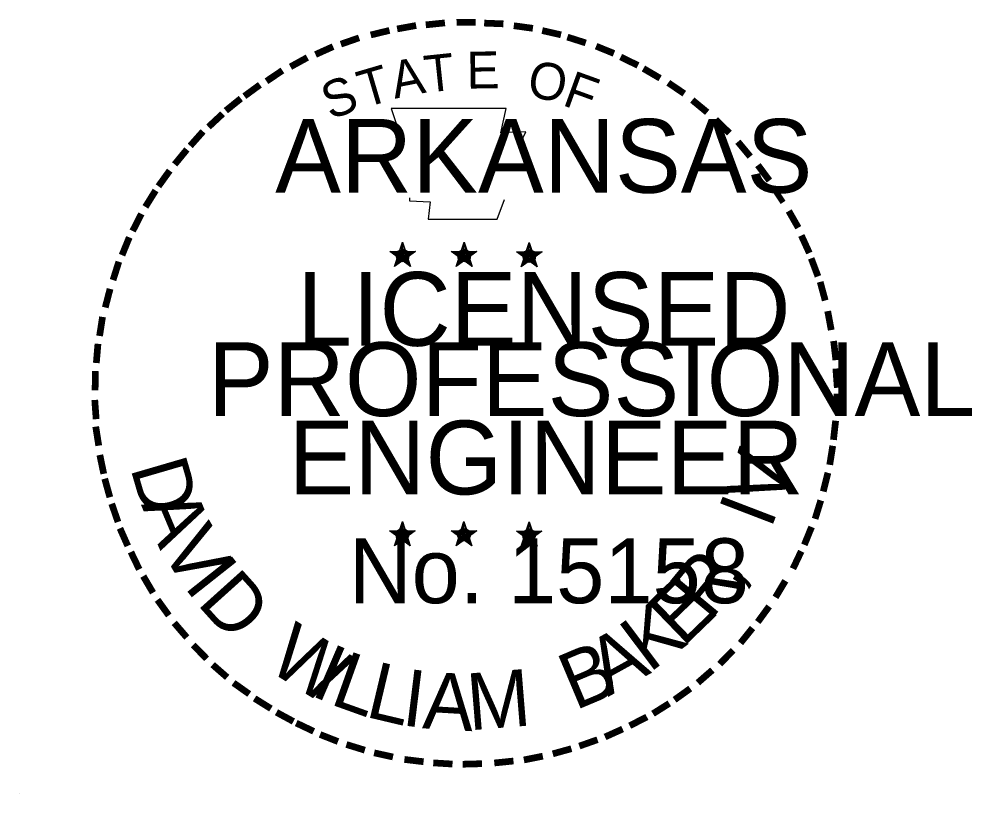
# Model space of a CAD drawing. Extents: x 1416408 to 1429341, y 372694 to 383211.
# Drawn here: x 1429125 to 1429341.3, y 374183.4 to 374359.3 of the extents above; entities that cross this region are included whole.
import ezdxf

# ---------------------------------------------------------------- set-up
doc = ezdxf.new("R2010")
doc.units = 0
doc.layers.add('R_Border PE', color=7, linetype='Continuous')
doc.layers.add('R_No Plot', color=7, linetype='Continuous')

msp = doc.modelspace()

# ---------------------------------------------------------------- linework, layer by layer
at = {"layer": 'R_Border PE'}
for p, q in [((1429212.11, 374308.64), (1429211.76, 374306.54)), ((1429212.11, 374305.59), (1429212.11, 374308.64)), ((1429212.11, 374308.64), (1429212.52, 374306.55)), ((1429226.09, 374308.64), (1429225.74, 374306.54)), ((1429226.09, 374305.59), (1429226.09, 374308.64)), ((1429226.09, 374308.64), (1429226.5, 374306.55)), ((1429240.85, 374308.54), (1429240.51, 374306.43)), ((1429240.85, 374305.49), (1429240.85, 374308.54)), ((1429240.85, 374308.54), (1429241.27, 374306.45)), ((1429209.18, 374306.52), (1429212.11, 374305.59)), ((1429209.18, 374306.52), (1429211.3, 374306.14)), ((1429209.18, 374306.52), (1429211.17, 374305.5)), ((1429215.01, 374306.52), (1429212.11, 374305.59)), ((1429215.01, 374306.52), (1429212.62, 374306.11)), ((1429215.01, 374306.52), (1429213.3, 374305.66)), ((1429223.16, 374306.52), (1429226.09, 374305.59)), ((1429223.16, 374306.52), (1429225.28, 374306.14)), ((1429223.16, 374306.52), (1429225.15, 374305.5)), ((1429228.99, 374306.52), (1429226.09, 374305.59)), ((1429228.99, 374306.52), (1429226.6, 374306.11)), ((1429228.99, 374306.52), (1429227.28, 374305.66)), ((1429237.93, 374306.42), (1429240.85, 374305.49)), ((1429237.93, 374306.42), (1429240.05, 374306.04)), ((1429237.93, 374306.42), (1429239.92, 374305.4)), ((1429243.76, 374306.42), (1429240.85, 374305.49)), ((1429243.76, 374306.42), (1429241.37, 374306.01)), ((1429243.76, 374306.42), (1429242.05, 374305.56)), ((1429210.3, 374303.1), (1429212.11, 374305.59)), ((1429210.3, 374303.1), (1429211.35, 374305.15)), ((1429210.3, 374303.1), (1429212.09, 374304.92)), ((1429213.89, 374303.1), (1429212.09, 374304.89)), ((1429213.89, 374303.1), (1429212.11, 374305.59)), ((1429213.89, 374303.1), (1429212.74, 374305.54)), ((1429224.28, 374303.1), (1429226.09, 374305.59)), ((1429224.28, 374303.1), (1429225.33, 374305.15)), ((1429224.28, 374303.1), (1429226.07, 374304.92)), ((1429227.87, 374303.1), (1429226.07, 374304.89)), ((1429227.87, 374303.1), (1429226.09, 374305.59)), ((1429227.87, 374303.1), (1429226.72, 374305.54)), ((1429239.05, 374303), (1429240.85, 374305.49)), ((1429239.05, 374303), (1429240.1, 374305.04)), ((1429239.05, 374303), (1429240.84, 374304.82)), ((1429242.64, 374303), (1429240.84, 374304.79)), ((1429242.64, 374303), (1429240.85, 374305.49)), ((1429242.64, 374303), (1429241.49, 374305.44)), ((1429212.07, 374245.24), (1429211.73, 374243.13)), ((1429212.07, 374242.19), (1429212.07, 374245.24)), ((1429212.07, 374245.24), (1429212.48, 374243.15)), ((1429226.04, 374245.24), (1429225.7, 374243.13)), ((1429226.04, 374242.19), (1429226.04, 374245.24)), ((1429226.04, 374245.24), (1429226.45, 374243.15)), ((1429240.84, 374245.16), (1429240.49, 374243.05)), ((1429240.84, 374242.1), (1429240.84, 374245.16)), ((1429240.84, 374245.16), (1429241.25, 374243.07)), ((1429209.15, 374243.12), (1429212.07, 374242.19)), ((1429209.15, 374243.12), (1429211.27, 374242.74)), ((1429209.15, 374243.12), (1429211.13, 374242.1)), ((1429210.26, 374239.7), (1429212.07, 374242.19)), ((1429210.26, 374239.7), (1429211.32, 374241.74)), ((1429210.26, 374239.7), (1429212.05, 374241.52)), ((1429213.85, 374239.7), (1429212.05, 374241.49)), ((1429214.98, 374243.12), (1429212.07, 374242.19)), ((1429213.85, 374239.7), (1429212.07, 374242.19)), ((1429214.98, 374243.12), (1429212.58, 374242.71)), ((1429213.85, 374239.7), (1429212.71, 374242.14)), ((1429214.98, 374243.12), (1429213.27, 374242.26)), ((1429223.12, 374243.12), (1429226.04, 374242.19)), ((1429223.12, 374243.12), (1429225.24, 374242.74)), ((1429223.12, 374243.12), (1429225.11, 374242.1)), ((1429224.24, 374239.7), (1429226.04, 374242.19)), ((1429224.24, 374239.7), (1429225.29, 374241.74)), ((1429224.24, 374239.7), (1429226.03, 374241.52)), ((1429227.83, 374239.7), (1429226.03, 374241.49)), ((1429228.95, 374243.12), (1429226.04, 374242.19)), ((1429227.83, 374239.7), (1429226.04, 374242.19)), ((1429228.95, 374243.12), (1429226.56, 374242.71)), ((1429227.83, 374239.7), (1429226.68, 374242.14)), ((1429228.95, 374243.12), (1429227.24, 374242.26)), ((1429237.92, 374243.03), (1429240.84, 374242.1)), ((1429237.92, 374243.03), (1429240.03, 374242.66)), ((1429237.92, 374243.03), (1429239.9, 374242.01)), ((1429239.03, 374239.62), (1429240.84, 374242.1)), ((1429239.03, 374239.62), (1429240.08, 374241.66)), ((1429239.03, 374239.62), (1429240.82, 374241.43)), ((1429242.62, 374239.62), (1429240.82, 374241.41)), ((1429243.74, 374243.03), (1429240.84, 374242.1)), ((1429242.62, 374239.62), (1429240.84, 374242.1)), ((1429243.74, 374243.03), (1429241.35, 374242.62)), ((1429242.62, 374239.62), (1429241.47, 374242.05)), ((1429243.74, 374243.03), (1429242.04, 374242.18))]:
    msp.add_line(p, q, dxfattribs=at)
for points in [[(1429209.53, 374338.99), (1429211.78, 374332.06)], [(1429238.92, 374331.27), (1429240.11, 374333.64), (1429234.37, 374333.44), (1429235.61, 374338.99), (1429209.53, 374338.99)], [(1429213.65, 374318.7), (1429213.65, 374317.97), (1429218.36, 374317.81), (1429217.91, 374313.85), (1429233.56, 374313.85), (1429235.25, 374318.34)], [(1429212.11, 374308.64), (1429213.89, 374303.1), (1429209.18, 374306.52), (1429215.01, 374306.52), (1429210.3, 374303.1), (1429212.11, 374308.64)], [(1429226.09, 374308.64), (1429227.87, 374303.1), (1429223.16, 374306.52), (1429228.99, 374306.52), (1429224.28, 374303.1), (1429226.09, 374308.64)], [(1429240.85, 374308.54), (1429242.64, 374303), (1429237.93, 374306.42), (1429243.76, 374306.42), (1429239.05, 374303), (1429240.85, 374308.54)], [(1429212.07, 374245.24), (1429213.85, 374239.7), (1429209.15, 374243.12), (1429214.98, 374243.12), (1429210.26, 374239.7), (1429212.07, 374245.24)], [(1429226.04, 374245.24), (1429227.83, 374239.7), (1429223.12, 374243.12), (1429228.95, 374243.12), (1429224.24, 374239.7), (1429226.04, 374245.24)], [(1429240.84, 374245.16), (1429242.62, 374239.62), (1429237.92, 374243.03), (1429243.74, 374243.03), (1429239.03, 374239.62), (1429240.84, 374245.16)]]:
    msp.add_lwpolyline(points, dxfattribs=at)
for centre, radius in [((1429212.1, 374305.58), 1.44), ((1429212.1, 374305.58), 1.21), ((1429212.1, 374305.58), 0.969), ((1429212.1, 374305.58), 0.83), ((1429212.1, 374305.58), 0.626), ((1429226.08, 374305.58), 1.44), ((1429226.08, 374305.58), 1.21), ((1429226.08, 374305.58), 0.969), ((1429226.08, 374305.58), 0.83), ((1429226.08, 374305.58), 0.626), ((1429240.85, 374305.48), 1.44), ((1429240.85, 374305.48), 1.21), ((1429240.85, 374305.48), 0.969), ((1429240.85, 374305.48), 0.83), ((1429212.1, 374305.58), 0.415), ((1429212.1, 374305.58), 0.248), ((1429226.08, 374305.58), 0.415), ((1429226.08, 374305.58), 0.248), ((1429240.85, 374305.48), 0.626), ((1429240.85, 374305.48), 0.415), ((1429240.85, 374305.48), 0.248), ((1429212.06, 374242.18), 1.44), ((1429212.06, 374242.18), 1.21), ((1429226.04, 374242.18), 1.44), ((1429226.04, 374242.18), 1.21), ((1429240.83, 374242.1), 1.44), ((1429212.06, 374242.18), 0.969), ((1429212.06, 374242.18), 0.83), ((1429212.06, 374242.18), 0.626), ((1429212.06, 374242.18), 0.415), ((1429212.06, 374242.18), 0.248), ((1429226.04, 374242.18), 0.969), ((1429226.04, 374242.18), 0.83), ((1429226.04, 374242.18), 0.626), ((1429226.04, 374242.18), 0.415), ((1429226.04, 374242.18), 0.248), ((1429240.83, 374242.1), 1.21), ((1429240.83, 374242.1), 0.969), ((1429240.83, 374242.1), 0.83), ((1429240.83, 374242.1), 0.626), ((1429240.83, 374242.1), 0.415), ((1429240.83, 374242.1), 0.248)]:
    msp.add_circle(centre, radius, dxfattribs=at)
at = {"layer": 'R_No Plot'}
msp.add_line((1429125.04, 374183.36), (1429125.04, 374183.36), dxfattribs=at)

# ---------------------------------------------------------------- texts
at = {"layer": 'R_Border PE'}
for s, height, rotation, p in [('-', 13.4, 10.2193, (1429211, 374351.79)), ('-', 13.4, 5.8968, (1429217.1, 374352.72)), ('-', 13.4, 0.1862, (1429223.56, 374353.32)), ('-', 13.4, 357.743, (1429229.62, 374353.21)), ('-', 13.4, 352.1617, (1429235.85, 374352.74)), ('-', 13.4, 13.6302, (1429205.32, 374350.44)), ('-', 13.4, 347.2049, (1429241.87, 374351.79)), ('-', 13.4, 342.3362, (1429247.18, 374350.49)), ('-', 13.4, 24.3072, (1429193.74, 374346.17)), ('-', 13.4, 19.1761, (1429199.04, 374348.42)), ('-', 13.4, 337.8551, (1429253.34, 374348.62)), ('T', 8.37, 6.0228, (1429217.43, 374342.55)), ('E', 8.37, 0.8323, (1429226.68, 374343.47)), ('-', 13.4, 28.7918, (1429188.44, 374343.51)), ('A', 8.37, 11.2132, (1429210.32, 374341.16)), ('O', 8.37, 350.4515, (1429240.11, 374341.71)), ('-', 13.4, 334.1211, (1429258.62, 374346.35)), ('-', 13.4, 34.0636, (1429183.44, 374340.42)), ('T', 8.37, 16.4036, (1429203.4, 374339.06)), ('F', 8.37, 340.0707, (1429248.09, 374339.81)), ('-', 13.4, 329.6409, (1429263.47, 374343.98)), ('S', 8.37, 21.594, (1429195.75, 374336.29)), ('-', 13.4, 325.8627, (1429268.85, 374340.96)), ('-', 13.4, 36.2317, (1429178.6, 374337.11)), ('-', 13.4, 38.9507, (1429174.61, 374333.95)), ('-', 13.4, 320.5297, (1429273.96, 374337.39)), ('-', 13.4, 42.9622, (1429170.99, 374330.45)), ('-', 13.4, 315.5786, (1429278.97, 374333.31)), ('-', 13.4, 48.4231, (1429167.24, 374326.45)), ('-', 13.4, 50.6142, (1429163.86, 374322.38)), ('-', 13.4, 309.8797, (1429283.73, 374328.7)), ('-', 13.4, 306.6522, (1429288.13, 374323.66)), ('-', 13.4, 54.2325, (1429160.41, 374317.64)), ('-', 13.4, 58.0706, (1429157.69, 374313.22)), ('-', 11.72, 303.6753, (1429292.2, 374318.91)), ('-', 13.4, 62.8713, (1429155.06, 374308.08)), ('-', 13.4, 299.6684, (1429294.87, 374313.83)), ('-', 13.4, 294.6628, (1429297.58, 374308.7)), ('-', 13.4, 67.7743, (1429152.9, 374302.97)), ('-', 13.4, 72.3945, (1429151.06, 374297.69)), ('-', 13.4, 290.5728, (1429299.73, 374303.87)), ('-', 13.4, 285.1233, (1429301.69, 374299.02)), ('-', 13.4, 75.461, (1429149.41, 374291.72)), ('-', 13.4, 81.2013, (1429148.31, 374285.75)), ('-', 13.4, 280.5493, (1429303.37, 374292.8)), ('-', 13.4, 85.1863, (1429147.67, 374279.96)), ('-', 13.4, 276.5962, (1429304.72, 374286.38)), ('-', 13.4, 89.0622, (1429147.46, 374274.09)), ('-', 13.4, 274.3301, (1429305.23, 374280.33)), ('-', 13.4, 269.9407, (1429305.51, 374275.04)), ('-', 13.4, 94.1959, (1429147.76, 374268.02)), ('-', 13.4, 263.5172, (1429305.35, 374269.46)), ('-', 13.4, 98.9479, (1429148.36, 374262.44)), ('V', 12.89, 72.6573, (1429297.51, 374247.74)), ('-', 13.4, 260.9953, (1429304.76, 374263.99)), ('-', 13.4, 101.7149, (1429149.49, 374256.3)), ('D', 12.89, 286.2848, (1429150.23, 374257.46)), ('-', 13.4, 255.7626, (1429303.84, 374258.31)), ('-', 13.4, 105.4578, (1429150.85, 374251.32)), ('I', 12.89, 69.0301, (1429295.65, 374243.23)), ('-', 13.4, 252.8681, (1429302.32, 374252.28)), ('-', 13.4, 109.0874, (1429152.65, 374246.04)), ('A', 12.89, 292.7835, (1429152.68, 374249.07)), ('V', 12.89, 300.7936, (1429156.98, 374239.2)), ('-', 13.4, 114.0643, (1429154.77, 374241.05)), ('-', 13.4, 247.8887, (1429300.45, 374246.65)), ('-', 13.4, 115.7289, (1429157.33, 374235.87)), ('I', 12.89, 308.3502, (1429162.27, 374230.52)), ('R', 12.89, 50.3651, (1429281.84, 374222.39)), ('-', 13.4, 244.6197, (1429298.26, 374241.38)), ('-', 13.4, 120.4471, (1429160.31, 374230.97)), ('D', 12.89, 311.9774, (1429165.2, 374226.62)), ('E', 12.89, 44.0175, (1429275.69, 374216.47)), (',', 12.89, 57.4684, (1429287.89, 374229.78)), ('-', 13.4, 239.0712, (1429294.96, 374235.09)), ('-', 13.4, 125.8934, (1429163.69, 374226.27)), ('K', 12.89, 36.9143, (1429268.08, 374210.69)), ('-', 13.4, 233.8452, (1429291.6, 374229.62)), ('-', 13.4, 130.7181, (1429167.56, 374221.65)), ('W', 12.89, 328.0731, (1429180.93, 374211.83)), ('A', 12.89, 28.9042, (1429258.72, 374205.36)), ('-', 13.4, 231.2538, (1429288, 374224.88)), ('-', 13.4, 134.2238, (1429171.88, 374217.09)), ('B', 12.89, 22.8589, (1429251.22, 374202.23)), ('I', 12.89, 336.6877, (1429190.87, 374205.89)), ('L', 12.89, 340.3149, (1429195.3, 374203.85)), ('-', 13.4, 225.7653, (1429283.99, 374220.16)), ('-', 13.4, 138.9338, (1429176.28, 374213.2)), ('L', 12.89, 346.6625, (1429203.34, 374200.96)), ('I', 12.89, 353.0101, (1429211.64, 374198.98)), ('M', 12.89, 4.6473, (1429227.23, 374197.78)), ('-', 13.4, 221.0851, (1429279.62, 374215.9)), ('-', 13.4, 144.6463, (1429180.93, 374209.8)), ('A', 12.89, 356.6373, (1429216.47, 374198.27)), ('-', 13.4, 215.7363, (1429275.02, 374211.95)), ('-', 13.4, 148.0898, (1429185.63, 374206.7)), ('-', 13.4, 212.2491, (1429270.55, 374208.71)), ('-', 13.4, 151.5704, (1429190.48, 374203.98)), ('-', 13.4, 154.6002, (1429194.85, 374201.91)), ('-', 13.4, 207.3568, (1429265.88, 374205.81)), ('-', 13.4, 204.2516, (1429260.65, 374203.14)), ('-', 13.4, 158.5612, (1429200.07, 374199.78)), ('-', 13.4, 199.4643, (1429255.37, 374200.82)), ('-', 13.4, 162.7983, (1429205.82, 374198)), ('-', 13.4, 195.4743, (1429249.8, 374198.83)), ('-', 13.4, 167.5555, (1429211.81, 374196.63)), ('-', 13.4, 173.1155, (1429218.27, 374195.71)), ('-', 13.4, 185.8167, (1429237.54, 374196.06)), ('-', 13.4, 191.2858, (1429243.7, 374197.16)), ('-', 13.4, 176.5183, (1429224.54, 374195.26)), ('-', 13.4, 181.5918, (1429230.76, 374195.42))]:
    msp.add_text(s, height=height, rotation=rotation, dxfattribs=at).set_placement(p)
for s, height, p in [('ARKANSAS', 16.744, (1429183.18, 374319.83)), ('LICENSED', 16.744, (1429188.18, 374285.09)), ('PROFESSIONAL', 16.7441, (1429167.89, 374269.15)), ('ENGINEER', 16.744, (1429186.2, 374251.36)), ('No. 15158', 14.71, (1429199.94, 374226.66)), ('AAMU', 0.000167, (1429225.49, 374197.74))]:
    msp.add_text(s, height=height, dxfattribs=at).set_placement(p)

doc.saveas('drawing.dxf')
